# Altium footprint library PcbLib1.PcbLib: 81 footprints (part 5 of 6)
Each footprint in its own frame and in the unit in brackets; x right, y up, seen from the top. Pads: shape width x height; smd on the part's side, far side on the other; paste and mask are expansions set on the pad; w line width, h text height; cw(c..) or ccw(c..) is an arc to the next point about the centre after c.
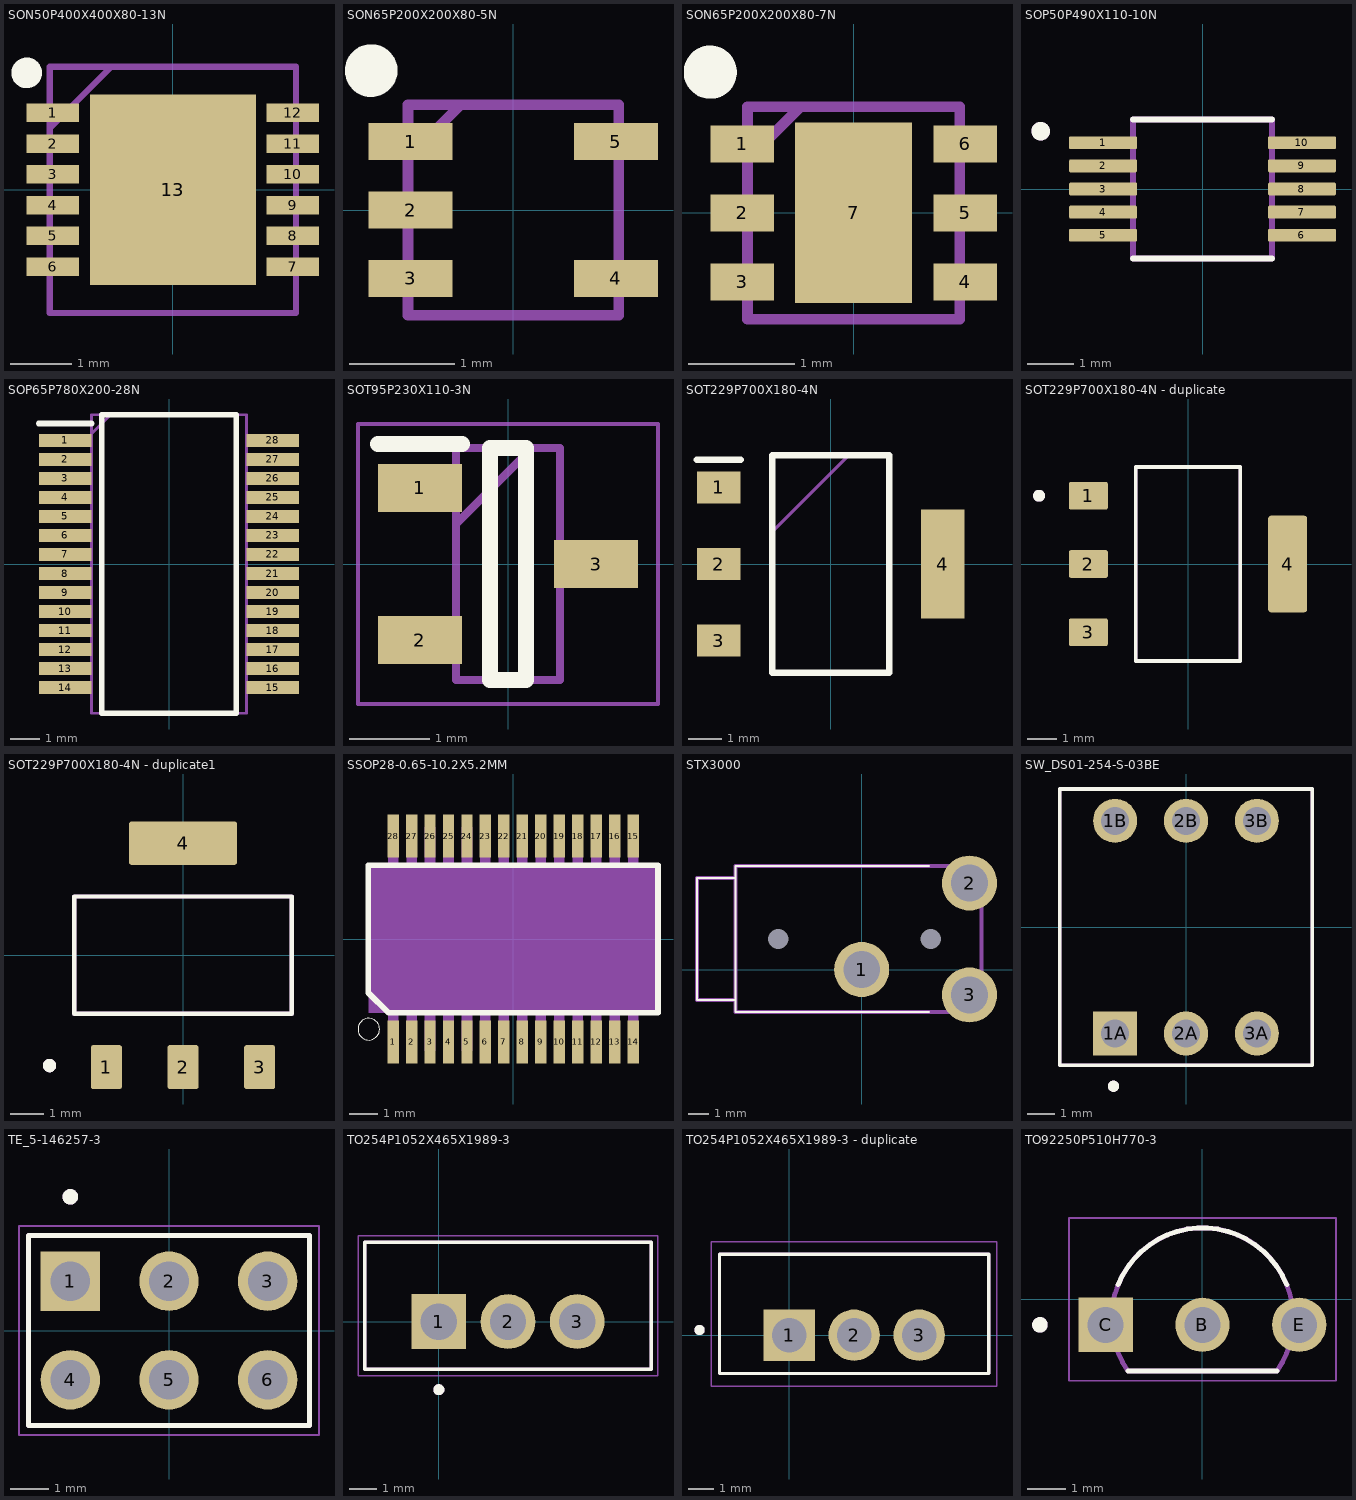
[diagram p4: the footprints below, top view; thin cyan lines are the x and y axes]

## SON50P400X400X80-13N [mm]
pads (13):
  rect 0.85x0.3 smd: 1(-1.95,1.25) 2(-1.95,0.75) 3(-1.95,0.25) 4(-1.95,-0.25) 5(-1.95,-0.75) 6(-1.95,-1.25) 7(1.95,-1.25) 8(1.95,-0.75) 9(1.95,-0.25) 10(1.95,0.25) 11(1.95,0.75) 12(1.95,1.25)
  rect 2.7x3.1 smd: 13(0,0)
Top Overlay:
  circle w0.25: c-2.375,1.9 r0.125
Mechanical 13:
  lines w0.1: -2,1 -1,2 ; -2,-2 -2,2 2,2 2,-2 -2,-2
3D body "LM5160ADNTR.stp": height 0.97, standoff 0, extent -2,-2 2,2

## SON65P200X200X80-5N [mm] "ADR03BUJZ-REEL7"
pads (5):
  rect 0.8x0.35 smd: 1(-0.975,0.65) 2(-0.975,0) 3(-0.975,-0.65) 4(0.975,-0.65) 5(0.975,0.65)
Top Overlay:
  circle w0.25: c-1.35,1.325 r0.125
Mechanical 13:
  lines w0.1: -1,0.5 -0.5,1 ; -1,-1 1,-1 1,1 -1,1 -1,-1
3D body "TLV76750DRVR.stp": height 0.8, standoff 0, extent -1.05,-1 1.05,1

## SON65P200X200X80-7N [mm]
pads (7):
  rect 0.6x0.35 smd: 1(-1.05,0.65) 2(-1.05,0) 3(-1.05,-0.65) 4(1.05,-0.65) 5(1.05,0) 6(1.05,0.65)
  rect 1.1x1.7 smd: 7(0,0)
Top Overlay:
  circle w0.25: c-1.35,1.325 r0.125
Mechanical 13:
  lines w0.1: -1,0.5 -0.5,1 ; -1,-1 -1,1 1,1 1,-1 -1,-1
3D body "TLV76750DRVR.stp": height 0.8, standoff 0, extent -1.05,-1 1.05,1

## SOP50P490X110-10N [mm]
pads (10):
  rrect25% 1.47x0.28 smd: 1(-2.15,1) 2(-2.15,0.5) 3(-2.15,0) 4(-2.15,-0.5) 5(-2.15,-1) 6(2.15,-1) 7(2.15,-0.5) 8(2.15,0) 9(2.15,0.5) 10(2.15,1)
Top Overlay:
  circle w0.2: c-3.5,1.25 r0.1
  lines w0.127: -1.5,-1.5 1.5,-1.5 ; -1.5,1.5 1.5,1.5
Mechanical 13:
  circle w0.2: c-3.5,1.25 r0.1
  lines w0.127: -1.5,-1.5 1.5,-1.5 1.5,1.5 -1.5,1.5 -1.5,-1.5
3D body "step_temp.STEP": height 1.1, standoff 0, extent -2.45,-1.5 2.45,1.5

## SOP65P780X200-28N [mm]
pads (28):
  rect 1.8x0.45 smd: 1(-3.55,4.225) 2(-3.55,3.575) 3(-3.55,2.925) 4(-3.55,2.275) 5(-3.55,1.625) 6(-3.55,0.975) 7(-3.55,0.325) 8(-3.55,-0.325) 9(-3.55,-0.975) 10(-3.55,-1.625) 11(-3.55,-2.275) 12(-3.55,-2.925) 13(-3.55,-3.575) 14(-3.55,-4.225) 15(3.55,-4.225) 16(3.55,-3.575) 17(3.55,-2.925) 18(3.55,-2.275) 19(3.55,-1.625) 20(3.55,-0.975) 21(3.55,-0.325) 22(3.55,0.325) 23(3.55,0.975) 24(3.55,1.625) 25(3.55,2.275) 26(3.55,2.925) 27(3.55,3.575) 28(3.55,4.225)
Top Overlay:
  lines w0.2: -4.45,4.8 -2.65,4.8 ; -2.3,-5.1 -2.3,5.1 2.3,5.1 2.3,-5.1 -2.3,-5.1
Mechanical 13:
  lines w0.1: -2.65,4.45 -2,5.1 ; -2.65,-5.1 -2.65,5.1 2.65,5.1 2.65,-5.1 -2.65,-5.1
3D body "ADS1256IDBR.stp": height 2, standoff 0, extent -3.9,-5.1 3.9,5.1

## SOT95P230X110-3N [mm]
pads (3):
  rect 1.05x0.6 smd: 1(-1.1,0.95) 2(-1.1,-0.95) 3(1.1,0)
Top Overlay:
  lines w0.2: -1.625,1.5 -0.575,1.5 ; -0.225,-1.45 -0.225,1.45 0.225,1.45 0.225,-1.45 -0.225,-1.45
Mechanical 13:
  lines w0.1: -0.65,0.5 0.3,1.45 ; -0.65,-1.45 -0.65,1.45 0.65,1.45 0.65,-1.45 -0.65,-1.45
Mechanical 15:
  lines w0.05: -1.875,-1.75 -1.875,1.75 1.875,1.75 1.875,-1.75 -1.875,-1.75
3D body "BC847C-QR.stp": height 0.95, standoff 0, extent -1.201,-1.448 1.199,1.452

## SOT229P700X180-4N [mm]
pads (4):
  rect 1.3x0.95 smd: 1(-3.35,2.29) 2(-3.35,0) 3(-3.35,-2.29)
  rect 1.3x3.25 smd: 4(3.35,0)
Top Overlay:
  lines w0.2: -4,3.115 -2.7,3.115 ; -1.752,-3.252 1.752,-3.252 1.752,3.252 -1.752,3.252 -1.752,-3.252
Mechanical 13:
  lines w0.1: -1.752,0.962 0.538,3.252 ; -1.752,-3.252 1.752,-3.252 1.752,3.252 -1.752,3.252 -1.752,-3.252
3D body "AMS1117-3.3.stp": height 1.8, standoff 0, extent -3.5,-3.253 3.5,3.253

## SOT229P700X180-4N - duplicate [mm]
height 1.8
pads (4):
  rrect15% 1.31x0.93 smd: 1(-3.345,2.29) 2(-3.345,0) 3(-3.345,-2.29)
  rrect15% 1.31x3.24 smd: 4(3.345,0)
Top Overlay:
  circle w0.2: c-5,2.29 r0.1
  lines w0.127: -1.753,-3.253 1.753,-3.253 1.753,3.253 -1.753,3.253 -1.753,-3.253
Mechanical 13:
  circle w0.2: c-5,2.29 r0.1
  lines w0.127: -1.753,-3.253 1.753,-3.253 1.753,3.253 -1.753,3.253 -1.753,-3.253
3D body "step_temp.STEP": height 1.8, standoff 0, extent -3.499,-3.251 3.499,3.251

## SOT229P700X180-4N - duplicate1 [mm]
height 1.8
pads (4):
  rrect15% 0.93x1.31 smd: 1(-2.29,-3.345) 2(0,-3.345) 3(2.29,-3.345)
  rrect15% 3.24x1.31 smd: 4(0,3.345)
Top Overlay:
  circle w0.2: c-3.99,-3.3 r0.1
  lines w0.127: -3.253,-1.753 -3.253,1.753 3.253,1.753 3.253,-1.753 -3.253,-1.753
Mechanical 13:
  circle w0.2: c-3.99,-3.3 r0.1
  lines w0.127: -3.253,-1.753 -3.253,1.753 3.253,1.753 3.253,-1.753 -3.253,-1.753
3D body "step_temp.STEP": height 1.8, standoff 0, extent -3.251,-3.499 3.251,3.499

## SSOP28-0.65-10.2X5.2MM [mm]
pads (28):
  rect 0.4x1.5 smd: 1(-4.225,-3.625) 2(-3.575,-3.625) 3(-2.925,-3.625) 4(-2.275,-3.625) 5(-1.625,-3.625) 6(-0.975,-3.625) 7(-0.325,-3.625) 8(0.325,-3.625) 9(0.975,-3.625) 10(1.625,-3.625) 11(2.275,-3.625) 12(2.925,-3.625) 13(3.575,-3.625) 14(4.225,-3.625) 15(4.225,3.625) 16(3.575,3.625) 17(2.925,3.625) 18(2.275,3.625) 19(1.625,3.625) 20(0.975,3.625) 21(0.325,3.625) 22(-0.325,3.625) 23(-0.975,3.625) 24(-1.625,3.625) 25(-2.275,3.625) 26(-2.925,3.625) 27(-3.575,3.625) 28(-4.225,3.625)
Top Overlay:
  circle w0: c-5.08,-3.175 r0.381
  lines w0.203: -5.1,-1.89 -5.1,2.6 5.1,2.6 5.1,-2.6 -4.39,-2.6 -5.1,-1.89
Mechanical 13:
  region: -4.047,-3.937 -4.403,-3.937 -4.403,-2.642 -4.047,-2.642
  region: -3.397,-3.937 -3.753,-3.937 -3.753,-2.642 -3.397,-2.642
  region: -2.747,-3.937 -3.103,-3.937 -3.103,-2.642 -2.747,-2.642
  region: -2.097,-3.937 -2.453,-3.937 -2.453,-2.642 -2.097,-2.642
  region: -1.447,-3.937 -1.803,-3.937 -1.803,-2.642 -1.447,-2.642
  region: -0.797,-3.937 -1.153,-3.937 -1.153,-2.642 -0.797,-2.642
  region: -0.147,-3.937 -0.503,-3.937 -0.503,-2.642 -0.147,-2.642
  region: 0.503,-3.937 0.147,-3.937 0.147,-2.642 0.503,-2.642
  region: 1.153,-3.937 0.797,-3.937 0.797,-2.642 1.153,-2.642
  region: 1.803,-3.937 1.447,-3.937 1.447,-2.642 1.803,-2.642
  region: 2.453,-3.937 2.097,-3.937 2.097,-2.642 2.453,-2.642
  region: 3.103,-3.937 2.747,-3.937 2.747,-2.642 3.103,-2.642
  region: 3.753,-3.937 3.397,-3.937 3.397,-2.642 3.753,-2.642
  region: 4.403,-3.937 4.047,-3.937 4.047,-2.642 4.403,-2.642
  region: 4.403,2.642 4.047,2.642 4.047,3.937 4.403,3.937
  region: 3.753,2.642 3.397,2.642 3.397,3.937 3.753,3.937
  region: 3.103,2.642 2.747,2.642 2.747,3.937 3.103,3.937
  region: 2.453,2.642 2.097,2.642 2.097,3.937 2.453,3.937
  region: 1.803,2.642 1.447,2.642 1.447,3.937 1.803,3.937
  region: 1.153,2.642 0.797,2.642 0.797,3.937 1.153,3.937
  region: 0.503,2.642 0.147,2.642 0.147,3.937 0.503,3.937
  region: -0.147,2.642 -0.503,2.642 -0.503,3.937 -0.147,3.937
  region: -0.797,2.642 -1.153,2.642 -1.153,3.937 -0.797,3.937
  region: -1.447,2.642 -1.803,2.642 -1.803,3.937 -1.447,3.937
  region: -2.097,2.642 -2.453,2.642 -2.453,3.937 -2.097,3.937
  region: -2.747,2.642 -3.103,2.642 -3.103,3.937 -2.747,3.937
  region: -3.397,2.642 -3.753,2.642 -3.753,3.937 -3.397,3.937
  region: -4.047,2.642 -4.403,2.642 -4.403,3.937 -4.047,3.937
Mechanical 15:
  region: 5.08,-2.6 -5.08,-2.6 -5.08,2.6 5.08,2.6
3D body "step_temp.STEP": height 2, standoff 0, extent -5.1,-3.9 5.1,3.9

## STX3000 [mm]
pads (5):
  round 2.704 hole 1.803: 1(0,0) 2(5.3,4.25) 3(5.3,-1.25)
  round 0.5 hole 1 unplated: MH1(-4.1,1.5) MH2(3.4,1.5)
Top Overlay:
  lines w0.1: -6.2,-2.1 3.3,-2.1 -6.2,-2.1 ; -6.2,-2.1 -6.2,-1.5 ; -6.2,-2.1 -6.2,-1.5 ; -6.2,-1.5 -6.2,4.5 ; -6.2,-1.5 -8.1,-1.5 -8.1,4.5 -6.2,4.5 ; -6.2,4.5 -6.2,5.1 ; -6.2,4.5 -6.2,5.1 ; -6.2,5.1 3.3,5.1 -6.2,5.1
Mechanical 13:
  lines w0.2: -8.1,-1.5 -6.2,-1.5 -6.2,4.5 -8.1,4.5 -8.1,-1.5 ; -6.2,-2.1 -6.2,5.1 5.9,5.1 5.9,-2.1 -6.2,-2.1
3D body "STX-3000.stp": height 6, standoff -2.5, extent -8.1,-2.1 5.9,5.1

## SW_DS01-254-S-03BE [mm]
height 7
pads (6):
  rect 1.58x1.58 / inner round 1.58 / far side rect 1.58x1.58 hole 1: 1A(-2.54,-3.81)
  round 1.58 hole 1: 1B(-2.54,3.81) 2A(0,-3.81) 2B(0,3.81) 3A(2.54,-3.81) 3B(2.54,3.81)
Top Overlay:
  circle w0.2: c-2.6,-5.7 r0.1
  lines w0.127: -4.52,-4.95 -4.52,4.95 4.52,4.95 4.52,-4.95 -4.52,-4.95
Mechanical 13:
  circle w0.2: c-2.6,-5.7 r0.1
  lines w0.127: -4.52,-4.95 -4.52,4.95 4.52,4.95 4.52,-4.95 -4.52,-4.95
3D body "A6E-3104-N--3DModel-STEP-273799.STEP": height 7.05, standoff -3.2, extent -4.39,-4.95 4.59,4.95

## TE_5-146257-3 [mm]
pads (6):
  rect 1.53x1.53 / inner round 1.53 / far side rect 1.53x1.53 hole 1.02: 1(-2.54,1.27)
  round 1.53 hole 1.02: 2(0,1.27) 3(2.54,1.27) 4(-2.54,-1.27) 5(0,-1.27) 6(2.54,-1.27)
Top Overlay:
  circle w0.2: c-2.54,3.44 r0.1
  lines w0.127: -3.61,-2.44 3.61,-2.44 3.61,2.44 -3.61,2.44 -3.61,-2.44
Mechanical 13:
  circle w0.2: c-2.54,3.44 r0.1
  lines w0.127: -3.61,-2.44 3.61,-2.44 3.61,2.44 -3.61,2.44 -3.61,-2.44
Mechanical 15:
  lines w0.05: -3.86,-2.69 3.86,-2.69 3.86,2.69 -3.86,2.69 -3.86,-2.69
3D body "step_temp.STEP": height 5.33, standoff -5.84, extent -3.339,-2.327 3.875,2.55

## TO254P1052X465X1989-3 [mm]
pads (3):
  rect 2.01x2.01 hole 1.34: 1(0,0)
  round 2.01 hole 1.34: 2(2.54,0) 3(5.08,0)
Top Overlay:
  circle w0.2: c0,-2.5 r0.1
  lines w0.127: -2.72,-1.743 -2.72,2.907 7.8,2.907 7.8,-1.743 -2.72,-1.743
Mechanical 13:
  circle w0.2: c0,-2.5 r0.1
  lines w0.127: -2.72,-1.743 7.8,-1.743 7.8,2.907 -2.72,2.907 -2.72,-1.743
Mechanical 15:
  lines w0.05: -2.97,-1.993 8.05,-1.993 8.05,3.157 -2.97,3.157 -2.97,-1.993
3D body "IRF540.STEP": height 19.84, standoff -10.19, extent -2.522,-1.695 7.575,2.75

## TO254P1052X465X1989-3 - duplicate [mm]
pads (3):
  rect 2.01x2.01 hole 1.34: 1(0,0)
  round 2.01 hole 1.34: 2(2.54,0) 3(5.08,0)
Top Overlay:
  circle w0.2: c-3.5,0.2 r0.1
  lines w0.127: -2.72,-1.5 7.8,-1.5 7.8,3.16 -2.72,3.16 -2.72,-1.5
Mechanical 13:
  circle w0.2: c-3.5,0.2 r0.1
  lines w0.127: -2.72,-1.5 7.8,-1.5 7.8,3.16 -2.72,3.16 -2.72,-1.5
Mechanical 15:
  lines w0.05: -3.04,-2.005 8.12,-2.005 8.12,3.655 -3.04,3.655 -3.04,-2.005

## TO92250P510H770-3 [mm]
pads (3):
  round 1.4 hole 0.93: B(0,-0.655) E(2.5,-0.655)
  rect 1.4x1.4 hole 0.93: C(-2.5,-0.655)
Top Overlay:
  circle w0.2: c-4.2,-0.655 r0.1
  lines w0.127: -2.179,0.38 cw(c0,-0.5) 2.179,0.38 ; -1.924,-1.85 1.924,-1.85 -1.924,-1.85
Mechanical 13:
  circle w0.2: c-4.2,-0.655 r0.1
  lines w0.127: -1.925,-1.848 cw(c0,-0.5) 1.925,-1.848 ; -1.924,-1.85 1.924,-1.85
Mechanical 15:
  lines w0.05: -3.45,-2.1 -3.45,2.1 3.45,2.1 3.45,-2.1 -3.45,-2.1
3D body "step_temp.STEP": height 5.33, standoff -15.62, extent -2.38,-1.43 2.38,2.19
